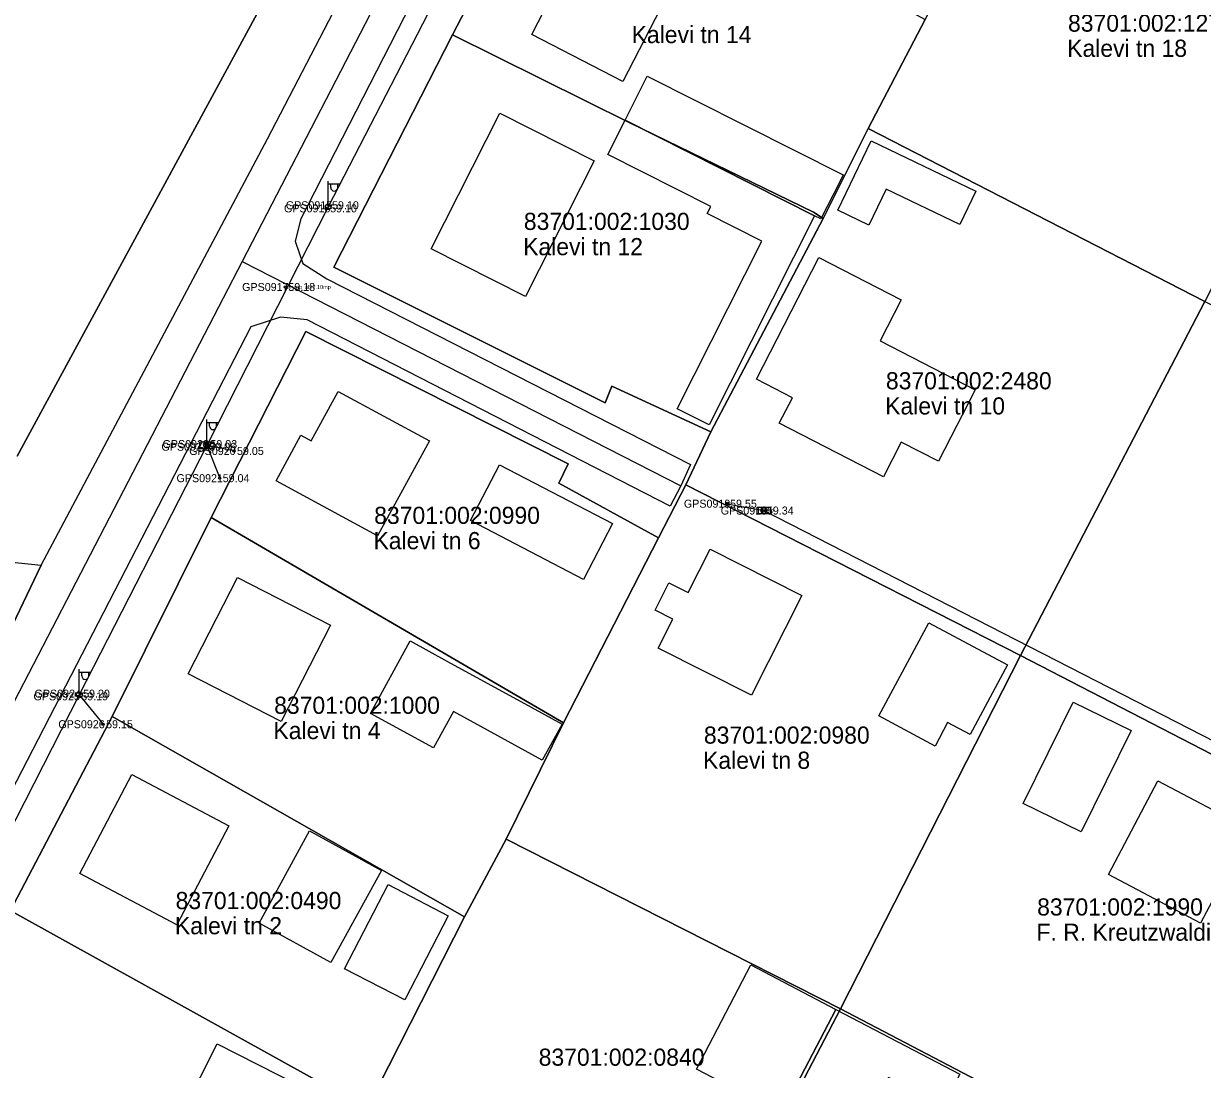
# Model space of a CAD drawing. Extents: x 580119 to 583377, y 6518915 to 6520820.
# Drawn here: x 581401 to 581504.1, y 6520038.7 to 6520130.2 of the extents above; entities that cross this region are included whole.
import ezdxf

# ---------------------------------------------------------------- set-up
doc = ezdxf.new("R2010")
doc.units = 0
for name, color, linetype in [('ELRAJATISMP', 7, 'Continuous'), ('Hoone Elu- või ühiskondlik hoone', 7, 'Continuous'), ('Hoone Kõrval- või tootmishoone', 7, 'Continuous'), ('L_AADRESS', 7, 'Continuous'), ('MAAMUDEL', 7, 'Continuous'), ('MOOTKORG-EH2000', 7, 'Continuous'), ('MOOTMPUNKT', 7, 'Continuous'), ('MOOTNR', 7, 'Continuous'), ('MPOHULIIN', 7, 'Continuous'), ('PIIR', 7, 'Continuous'), ('POST', 7, 'Continuous'), ('Rippe kõrgus', 7, 'Continuous'), ('Tee Liiklusala', 7, 'Continuous'), ('Tee Parkla', 7, 'Continuous'), ('Tee Tänav Kruuskate', 7, 'Continuous'), ('Tee Tänav Püsikate', 7, 'Continuous'), ('TUNNUS', 7, 'Continuous')]:
    doc.layers.add(name, color=color, linetype=linetype)

msp = doc.modelspace()

# ---------------------------------------------------------------- linework, layer by layer
at = {"layer": 'ELRAJATISMP'}
for p, q in [((581416.92, 6520093.59), (581416.92, 6520092.99)), ((581417.19, 6520093.59), (581417.19, 6520092.99)), ((581465.64, 6520087.89), (581465.64, 6520087.3)), ((581465.91, 6520087.89), (581465.91, 6520087.3))]:
    msp.add_line(p, q, dxfattribs=at)
for points in [[(581416.45, 6520093.59), (581417.65, 6520093.59), (581417.65, 6520092.99), (581416.45, 6520092.99)], [(581465.18, 6520087.89), (581466.37, 6520087.89), (581466.37, 6520087.3), (581465.18, 6520087.3)]]:
    msp.add_lwpolyline(points, close=True, dxfattribs=at)
at = {"layer": 'Hoone Elu- või ühiskondlik hoone'}
for points in [[(581459.59, 6520137.08), (581453.44, 6520125.11), (581445.47, 6520129.21), (581451.61, 6520141.18)], [(581436.68, 6520110.49), (581442.68, 6520122.35), (581450.94, 6520118.17), (581444.94, 6520106.31)], [(581484.27, 6520098.15), (581481.06, 6520091.9), (581477.8, 6520093.57), (581476.23, 6520090.53), (581467.12, 6520095.22), (581468.27, 6520097.46), (581465.12, 6520099.08), (581470.59, 6520109.73), (581477.79, 6520106.02), (581475.94, 6520102.42)], [(581436.52, 6520093.69), (581431.99, 6520085.37), (581423.12, 6520090.2), (581425.28, 6520094.17), (581426.19, 6520093.68), (581428.54, 6520098.01)], [(581461.07, 6520084.22), (581469.1, 6520080.15), (581464.68, 6520071.43), (581456.54, 6520075.55), (581457.82, 6520078.08), (581456.26, 6520078.87), (581457.47, 6520081.26), (581459.14, 6520080.41)], [(581427.86, 6520077.56), (581423.56, 6520069.15), (581415.42, 6520073.31), (581419.73, 6520081.72)], [(581405.93, 6520055.84), (581410.5, 6520064.5), (581418.99, 6520060.02), (581414.42, 6520051.36)], [(581508.31, 6520059.68), (581503.98, 6520051.49), (581495.92, 6520055.75), (581500.25, 6520063.94)]]:
    msp.add_lwpolyline(points, close=True, dxfattribs=at)
at = {"layer": 'Hoone Kõrval- või tootmishoone'}
for points in [[(581472.71, 6520116.95), (581472.38, 6520116.29), (581470.76, 6520113.09), (581470.21, 6520113.37), (581453.64, 6520121.73), (581455.58, 6520125.59)], [(581470.21, 6520113.37), (581460.98, 6520095.08), (581458.2, 6520096.48), (581465.61, 6520111.15), (581460.83, 6520113.56), (581461.15, 6520114.18), (581452.12, 6520118.74), (581453.64, 6520121.73)], [(581475.15, 6520119.92), (581484.32, 6520115.53), (581482.92, 6520112.6), (581476.46, 6520115.69), (581474.96, 6520112.55), (581472.24, 6520113.85)], [(581452.54, 6520086.45), (581450, 6520081.57), (581440.12, 6520086.71), (581442.66, 6520091.6)], [(581487.1, 6520074.09), (581483.83, 6520067.99), (581481.85, 6520069.05), (581480.75, 6520066.99), (581475.84, 6520069.62), (581480.22, 6520077.77)], [(581438.11, 6520074.39), (581445.42, 6520070.39), (581448.12, 6520068.91), (581446.39, 6520065.75), (581438.62, 6520070), (581436.88, 6520066.84), (581431.37, 6520069.85), (581434.84, 6520076.18)], [(581488.47, 6520061.98), (581492.84, 6520070.84), (581497.91, 6520068.34), (581493.54, 6520059.48)], [(581432.33, 6520056.12), (581427.91, 6520048.05), (581421.62, 6520051.5), (581426.04, 6520059.57)], [(581429.1, 6520047.52), (581432.91, 6520054.87), (581438.17, 6520052.14), (581434.36, 6520044.79)], [(581472.07, 6520043.96), (581467.31, 6520034.85), (581459.88, 6520038.74), (581464.65, 6520047.85)], [(581482.91, 6520038.3), (581481.45, 6520035.51), (581476.69, 6520038), (581474.89, 6520034.57), (581472.92, 6520035.6), (581470.24, 6520030.48), (581466.14, 6520032.62), (581467.31, 6520034.85), (581472.07, 6520043.96)], [(581430.35, 6520034.66), (581427.39, 6520028.84), (581415.01, 6520035.13), (581417.96, 6520040.94)]]:
    msp.add_lwpolyline(points, close=True, dxfattribs=at)
at = {"layer": 'MOOTMPUNKT'}
for centre in [(581427.58, 6520114.02), (581427.74, 6520114.29), (581423.92, 6520107.14), (581417, 6520093.17), (581417.1, 6520093.4), (581419.43, 6520092.8), (581418.18, 6520090.42), (581462.56, 6520088.19), (581465.78, 6520087.59), (581405.81, 6520071.34), (581405.97, 6520071.57), (581407.98, 6520068.9)]:
    msp.add_circle(centre, 0.1, dxfattribs=at)
at = {"layer": 'MPOHULIIN'}
for p, q in [((581417.05, 6520093.29), (581418.18, 6520090.42)), ((581419.43, 6520092.8), (581417.05, 6520093.29)), ((581465.78, 6520087.59), (581509.06, 6520065.4)), ((581405.89, 6520071.46), (581407.98, 6520068.9))]:
    msp.add_line(p, q, dxfattribs=at)
msp.add_lwpolyline([(581458.59, 6520174.68), (581447.28, 6520152.5), (581438.19, 6520134.57), (581427.66, 6520114.16), (581417.05, 6520093.29), (581405.89, 6520071.46), (581390.84, 6520041.99), (581386.07, 6520026.02)], dxfattribs=at)
at = {"layer": 'PIIR'}
for points in [[(581400.45, 6520092.33), (581500.71, 6520277.24), (581533.26, 6520341.75), (581558.12, 6520389.79), (581657.24, 6520583.27)], [(581384.33, 6520418.25), (581405.05, 6520409.44), (581419.35, 6520443.1), (581449.24, 6520446.57), (581558.12, 6520389.79), (581533.26, 6520341.75), (581494.52, 6520360.71), (581462.65, 6520295.82), (581500.71, 6520277.24), (581400.45, 6520092.33)], [(581448.09, 6520147.64), (581438.54, 6520129.2), (581428.17, 6520108.86), (581451.88, 6520097), (581452.49, 6520098.47), (581461.14, 6520094.47), (581458.96, 6520089.85), (581456.55, 6520085.21), (581447.84, 6520089.97), (581448.66, 6520091.66), (581425.72, 6520103.24), (581417.42, 6520086.99), (581408.78, 6520069.58), (581399.85, 6520052.55)]]:
    msp.add_lwpolyline(points, dxfattribs=at)
for points in [[(581479.88, 6520130.54), (581488.87, 6520148.2), (581491.13, 6520152.34), (581520.24, 6520137.28), (581504.34, 6520105.88), (581474.91, 6520121.01)], [(581448.09, 6520147.64), (581479.88, 6520130.54), (581474.91, 6520121.01), (581470.96, 6520113.13), (581470.13, 6520113.68), (581454.06, 6520121.5), (581438.54, 6520129.2)], [(581438.54, 6520129.2), (581454.06, 6520121.5), (581470.13, 6520113.68), (581470.96, 6520113.13), (581461.14, 6520094.47), (581452.49, 6520098.47), (581451.88, 6520097), (581428.17, 6520108.86)], [(581461.14, 6520094.47), (581470.96, 6520113.13), (581474.91, 6520121.01), (581504.34, 6520105.88), (581488.22, 6520074.9), (581458.96, 6520089.85)], [(581504.34, 6520105.88), (581533.26, 6520091.07), (581519.81, 6520064.28), (581517.28, 6520059.91), (581488.22, 6520074.9)], [(581425.72, 6520103.24), (581448.66, 6520091.66), (581447.84, 6520089.97), (581456.55, 6520085.21), (581448.26, 6520069.01), (581417.42, 6520086.99)], [(581448.26, 6520069.01), (581456.55, 6520085.21), (581458.96, 6520089.85), (581488.22, 6520074.9), (581472.48, 6520044), (581443.23, 6520058.84)], [(581417.42, 6520086.99), (581448.26, 6520069.01), (581443.23, 6520058.84), (581439.6, 6520052.04), (581408.78, 6520069.58)], [(581488.22, 6520074.9), (581517.28, 6520059.91), (581514.94, 6520055.34), (581501.39, 6520028.88), (581472.48, 6520044)], [(581399.85, 6520052.55), (581408.78, 6520069.58), (581439.6, 6520052.04), (581431.08, 6520035.3), (581430.82, 6520035.45), (581400.17, 6520052.43)], [(581439.6, 6520052.04), (581443.23, 6520058.84), (581472.48, 6520044), (581459.24, 6520018.64), (581455.53, 6520020.52), (581431.08, 6520035.3)], [(581399.85, 6520052.55), (581400.17, 6520052.43), (581430.82, 6520035.45), (581431.08, 6520035.3), (581417.16, 6520008.29), (581386.35, 6520025.87)], [(581459.24, 6520018.64), (581472.48, 6520044), (581501.39, 6520028.88), (581487.59, 6520002.15), (581463.52, 6520016.06)]]:
    msp.add_lwpolyline(points, close=True, dxfattribs=at)
at = {"layer": 'POST'}
for p, q in [((581427.66, 6520114.41), (581427.66, 6520116.41)), ((581427.66, 6520116.16), (581428.66, 6520116.16)), ((581427.89, 6520115.84), (581427.89, 6520116.16)), ((581428.5, 6520115.84), (581428.5, 6520116.16)), ((581427.66, 6520114.16), (581427.66, 6520114.16)), ((581417.05, 6520093.54), (581417.05, 6520095.54)), ((581417.05, 6520095.29), (581418.05, 6520095.29)), ((581417.28, 6520094.97), (581417.28, 6520095.29)), ((581417.89, 6520094.97), (581417.89, 6520095.29)), ((581417.05, 6520093.29), (581417.05, 6520093.29)), ((581405.89, 6520071.71), (581405.89, 6520073.71)), ((581405.89, 6520073.46), (581406.89, 6520073.46)), ((581406.11, 6520073.13), (581406.11, 6520073.46)), ((581406.73, 6520073.13), (581406.73, 6520073.46)), ((581405.89, 6520071.46), (581405.89, 6520071.46))]:
    msp.add_line(p, q, dxfattribs=at)
msp.add_lwpolyline([(581462.56, 6520088.19), (581465.78, 6520087.59)], dxfattribs=at)
for centre, radius in [((581427.66, 6520114.16), 0.25), ((581417.05, 6520093.29), 0.25), ((581462.56, 6520088.19), 0.125), ((581462.56, 6520088.19), 0.105), ((581462.56, 6520088.19), 0.0851), ((581462.56, 6520088.19), 0.0651), ((581462.56, 6520088.19), 0.0451), ((581462.56, 6520088.19), 0.0251), ((581462.56, 6520088.19), 0.00511), ((581465.78, 6520087.59), 0.25), ((581405.89, 6520071.46), 0.25)]:
    msp.add_circle(centre, radius, dxfattribs=at)
for centre in [(581428.19, 6520115.84), (581417.59, 6520094.97), (581406.42, 6520073.13)]:
    msp.add_arc(centre, 0.306, 180, 0, dxfattribs=at)
at = {"layer": 'Tee Liiklusala'}
for points in [[(581398.16, 6520073.66), (581402.55, 6520082.81), (581422.36, 6520120.09), (581439.19, 6520152.49), (581449.34, 6520172.35), (581469.76, 6520211.65), (581406.17, 6520246.86), (581402.87, 6520241), (581366.58, 6520261.36)], [(581484.66, 6520227.52), (581458.05, 6520176.72), (581457.08, 6520173.79), (581457.4, 6520171.68), (581459.01, 6520169.74), (581491.68, 6520154.29), (581490.82, 6520152.48), (581489.96, 6520150.68), (581457.15, 6520166.25), (581453.83, 6520166.82), (581452.37, 6520166), (581425.27, 6520113.09), (581424.79, 6520111.14), (581425.44, 6520109.19), (581427.55, 6520107.84), (581459.36, 6520091.61), (581458.5, 6520089.74), (581457.59, 6520087.96), (581425.83, 6520104.26), (581423.49, 6520104.49), (581420.89, 6520103.67), (581395.58, 6520054.65)]]:
    msp.add_lwpolyline(points, dxfattribs=at)
at = {"layer": 'Tee Parkla'}
msp.add_lwpolyline([(581402.55, 6520082.81), (581398.16, 6520073.66), (581397.81, 6520076.82), (581396.6, 6520078.42), (581386.42, 6520084.22), (581360.65, 6520040.86), (581314.34, 6520068.96), (581320.79, 6520079.42), (581316.66, 6520082.57), (581341.87, 6520124.18), (581345.44, 6520122.34), (581359.84, 6520114.79), (581357.3, 6520110.56), (581350.79, 6520101.1), (581332.48, 6520069.27), (581359.51, 6520053.72), (581377.82, 6520085.56), (581382.56, 6520093), (581399.44, 6520083.13)], close=True, dxfattribs=at)
at = {"layer": 'Tee Tänav Kruuskate'}
msp.add_lwpolyline([(581420.13, 6520109.36), (581458.5, 6520089.74)], dxfattribs=at)
at = {"layer": 'Tee Tänav Püsikate'}
for points in [[(581452, 6520170.97), (581420.13, 6520109.36)], [(581420.13, 6520109.36), (581395.19, 6520061.26), (581375.29, 6520020.77)]]:
    msp.add_lwpolyline(points, dxfattribs=at)

# ---------------------------------------------------------------- texts
at = {"layer": 'L_AADRESS'}
for s, p in [('Kalevi tn 14', (581454.21, 6520128.47)), ('Kalevi tn 18', (581492.31, 6520127.27)), ('Kalevi tn 12', (581444.72, 6520109.92)), ('Kalevi tn 10', (581476.39, 6520095.99)), ('Kalevi tn 6', (581431.63, 6520084.21)), ('Kalevi tn 4', (581422.88, 6520067.6)), ('Kalevi tn 8', (581460.46, 6520065)), ('Kalevi tn 2', (581414.26, 6520050.53)), ('F. R. Kreutzwaldi tn 5', (581489.62, 6520049.96))]:
    msp.add_text(s, height=1.5, dxfattribs=at).set_placement(p)
at = {"layer": 'MAAMUDEL'}
msp.add_text(' kilp', height=0.35, dxfattribs=at).set_placement((581465.78, 6520087.42))
at = {"layer": 'MOOTKORG-EH2000'}
for s, p in [(' 59.10', (581427.74, 6520113.94)), (' 59.10', (581427.58, 6520113.67)), (' 59.18', (581423.92, 6520106.79)), (' 59.06', (581417, 6520092.82)), (' 59.03', (581417.1, 6520093.05)), (' 59.05', (581419.43, 6520092.45)), (' 59.04', (581418.18, 6520090.07)), (' 59.55', (581462.56, 6520087.84)), (' 59.34', (581465.78, 6520087.24)), (' 59.19', (581405.81, 6520070.99)), (' 59.20', (581405.97, 6520071.22)), (' 59.15', (581407.98, 6520068.55))]:
    msp.add_text(s, height=0.7, dxfattribs=at).set_placement(p)
at = {"layer": 'MOOTNR'}
for s, p in [('GPS0915 ', (581423.96, 6520113.94)), ('GPS0916 ', (581423.8, 6520113.67)), ('GPS0917 ', (581420.14, 6520106.79)), ('GPS0922 ', (581413.08, 6520092.82)), ('GPS0923 ', (581413.18, 6520093.05)), ('GPS0920 ', (581415.51, 6520092.45)), ('GPS0921 ', (581414.4, 6520090.07)), ('GPS0919 ', (581458.78, 6520087.84)), ('GPS0918 ', (581462, 6520087.24)), ('GPS0925 ', (581401.89, 6520070.99)), ('GPS0924 ', (581401.98, 6520071.22)), ('GPS0926 ', (581404.06, 6520068.55))]:
    msp.add_text(s, height=0.7, dxfattribs=at).set_placement(p)
at = {"layer": 'Rippe kõrgus'}
msp.add_text(' el_mp_ohl7.10mp', height=0.35, dxfattribs=at).set_placement((581423.92, 6520106.96))
at = {"layer": 'TUNNUS'}
for s, p in [('83701:002:1270', (581492.38, 6520129.47)), ('83701:002:1030', (581444.78, 6520112.13)), ('83701:002:2480', (581476.45, 6520098.19)), ('83701:002:0990', (581431.69, 6520086.42)), ('83701:002:1000', (581422.94, 6520069.81)), ('83701:002:0980', (581460.53, 6520067.2)), ('83701:002:0490', (581414.32, 6520052.73)), ('83701:002:1990', (581489.68, 6520052.17)), ('83701:002:0840', (581446.08, 6520039.03))]:
    msp.add_text(s, height=1.5, dxfattribs=at).set_placement(p)

doc.saveas('drawing.dxf')
